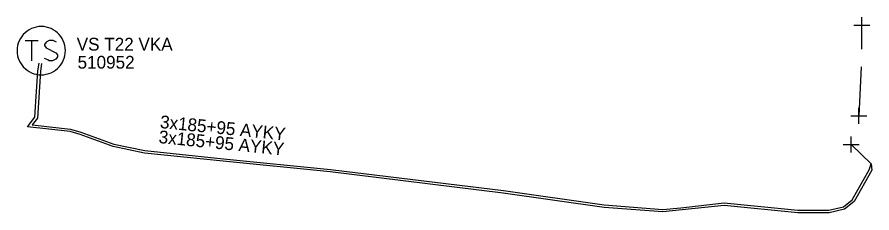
# Model space of a CAD drawing. Extents: x -536149 to -535465, y -1201639 to -1201298.
# Drawn here: x -536149 to -536082.1, y -1201322.4 to -1201307.1 of the extents above; entities that cross this region are included whole.
import ezdxf

# ---------------------------------------------------------------- set-up
doc = ezdxf.new("R2010")
doc.units = 0
for name, color, linetype in [('Vrstva 1', 7, 'Continuous'), ('Vrstva 25', 7, 'Continuous'), ('Vrstva 26', 7, 'Continuous'), ('Vrstva 27', 7, 'Continuous'), ('Vrstva 34', 7, 'Continuous'), ('Vrstva 5', 7, 'Continuous'), ('Vrstva 59', 7, 'Continuous'), ('Vrstva 6', 7, 'Continuous')]:
    doc.layers.add(name, color=color, linetype=linetype)

# ---------------------------------------------------------------- blocks, each defined once
blk = doc.blocks.new('NN800')
at = {"layer": 'Vrstva 1'}
for points in [[(-0.442, 0.442), (0.442, -0.442)], [(-0.442, -0.442), (0.442, 0.442)]]:
    blk.add_lwpolyline(points, dxfattribs=at)
blk = doc.blocks.new('NN610')
at = {"layer": 'Vrstva 6'}
for points in [[(1.883, -0.001), (1.872, 0.196), (1.841, 0.392), (1.79, 0.583), (1.718, 0.768), (1.629, 0.943), (1.521, 1.109), (1.397, 1.263), (1.257, 1.403), (1.103, 1.527), (0.937, 1.635), (0.761, 1.725), (0.577, 1.796), (0.19, 1.878), (0.19, 1.878), (-0.007, 1.889), (-0.205, 1.878), (-0.401, 1.847), (-0.591, 1.796), (-0.777, 1.725), (-0.952, 1.635), (-1.118, 1.527), (-1.272, 1.403), (-1.412, 1.263), (-1.536, 1.109), (-1.644, 0.943), (-1.734, 0.768), (-1.805, 0.583), (-1.856, 0.392), (-1.887, 0.196), (-1.898, -0.001), (-1.887, -0.199), (-1.856, -0.395), (-1.805, -0.585), (-1.734, -0.77), (-1.644, -0.946), (-1.536, -1.112), (-1.411, -1.266), (-1.272, -1.405), (-1.118, -1.53), (-0.952, -1.638), (-0.776, -1.728), (-0.591, -1.799), (-0.401, -1.85), (-0.205, -1.881), (-0.007, -1.892), (0.19, -1.881), (0.385, -1.85), (0.577, -1.799), (0.761, -1.728), (0.937, -1.638), (1.103, -1.53), (1.257, -1.405), (1.397, -1.266), (1.521, -1.112), (1.629, -0.946), (1.718, -0.77), (1.79, -0.585), (1.841, -0.395), (1.872, -0.199), (1.883, -0.001)], [(-1.269, 0.782), (-0.261, 0.782)], [(-0.765, 0.782), (-0.765, -0.792)], [(1.188, 0.656), (0.936, 0.782), (0.621, 0.782), (0.369, 0.656), (0.243, 0.468), (0.243, 0.404), (0.369, 0.216), (1.125, -0.162), (1.251, -0.32), (1.251, -0.478), (1.125, -0.666), (0.873, -0.792), (0.621, -0.792), (0.495, -0.73), (0.243, -0.604)]]:
    blk.add_lwpolyline(points, dxfattribs=at)

msp = doc.modelspace()

# ---------------------------------------------------------------- linework, layer by layer
at = {"layer": 'Vrstva 5'}
msp.add_lwpolyline([(-536147.055, -1201310.716), (-536147.14, -1201311.32), (-536147.372, -1201314.977), (-536147.777, -1201315.506), (-536144.78, -1201315.839), (-536143.972, -1201316.08), (-536141.395, -1201317.011), (-536138.977, -1201317.526), (-536132.83, -1201318.153), (-536124.444, -1201318.993), (-536110.921, -1201320.645), (-536103.025, -1201321.773), (-536098.446, -1201322.118), (-536097.03, -1201321.983), (-536093.653, -1201321.617), (-536087.88, -1201322.18), (-536085.459, -1201322.19), (-536084.311, -1201321.918), (-536083.625, -1201321.365), (-536082.306, -1201319.038), (-536082.138, -1201318.553), (-536082.089, -1201319.061), (-536083.47, -1201321.496), (-536084.22, -1201322.102), (-536085.436, -1201322.39), (-536087.89, -1201322.38), (-536093.652, -1201321.818), (-536098.444, -1201322.318), (-536103.046, -1201321.972), (-536110.948, -1201320.844), (-536124.466, -1201319.192), (-536132.85, -1201318.352), (-536139.008, -1201317.724), (-536141.45, -1201317.204), (-536144.034, -1201316.27), (-536144.82, -1201316.036), (-536148.152, -1201315.666), (-536147.568, -1201314.903), (-536147.34, -1201311.3), (-536147.252, -1201310.679)], dxfattribs=at)
at = {"layer": 'Vrstva 59'}
for points in [[(-536082.888, -1201309.606), (-536082.888, -1201307.714)], [(-536082.917, -1201310.983), (-536083.102, -1201314.806)], [(-536082.138, -1201318.553), (-536083.706, -1201317.048)]]:
    msp.add_lwpolyline(points, dxfattribs=at)

# ---------------------------------------------------------------- block references
at = {"layer": 'Vrstva 25', "rotation": 0.005252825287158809}
msp.add_blockref('NN610', (-536147.069, -1201309.71), dxfattribs=at)
at = {"layer": 'Vrstva 34'}
for p, rotation in [((-536082.888, -1201307.714), 44.999999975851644), ((-536083.102, -1201314.806), 45), ((-536083.706, -1201317.048), 45.00000009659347)]:
    msp.add_blockref('NN800', p, dxfattribs=dict(at, rotation=rotation))

# ---------------------------------------------------------------- texts
at = {"layer": 'Vrstva 26'}
msp.add_text('510952', height=1, dxfattribs=at).set_placement((-536144.235, -1201311.117))
at = {"layer": 'Vrstva 27'}
msp.add_text('VS T22 VKA', height=1, dxfattribs=at).set_placement((-536144.303, -1201309.707))
at = {"layer": 'Vrstva 6'}
for rotation, p in [(354.28, (-536137.818, -1201315.751)), (354.279, (-536137.925, -1201316.925))]:
    msp.add_text('3x185+95 AYKY', height=1, rotation=rotation, dxfattribs=at).set_placement(p)

doc.saveas('drawing.dxf')
